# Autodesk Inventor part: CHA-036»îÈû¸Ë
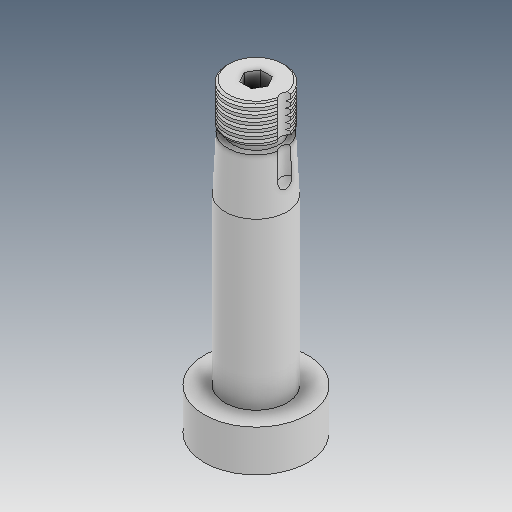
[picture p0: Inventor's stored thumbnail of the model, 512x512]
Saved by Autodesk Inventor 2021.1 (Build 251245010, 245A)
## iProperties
Created: 2019-12
Part Number: CHA-036»îÈû¸Ë
Material: Ogólny
Document SubType Name: Modeling
Designer: user
Density: 1 g/cm^3
Appearance: Domyślna
Author: user
Revision Number: ÈÎºÎ
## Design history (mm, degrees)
feature "ÇÐ³ý-Ðý×ª3"
node "Bryła1"
